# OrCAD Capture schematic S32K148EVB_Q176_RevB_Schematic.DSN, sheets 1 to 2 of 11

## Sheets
1 08. SAI AUDIO: size B; title: S32K148EVB-Q176; rev: B; company: NXP Semiconductors; note: SCH-29559 PDF: SPF-29559; note: 6501 William Cannon Drive West; note: Austin, TX 78735-8598
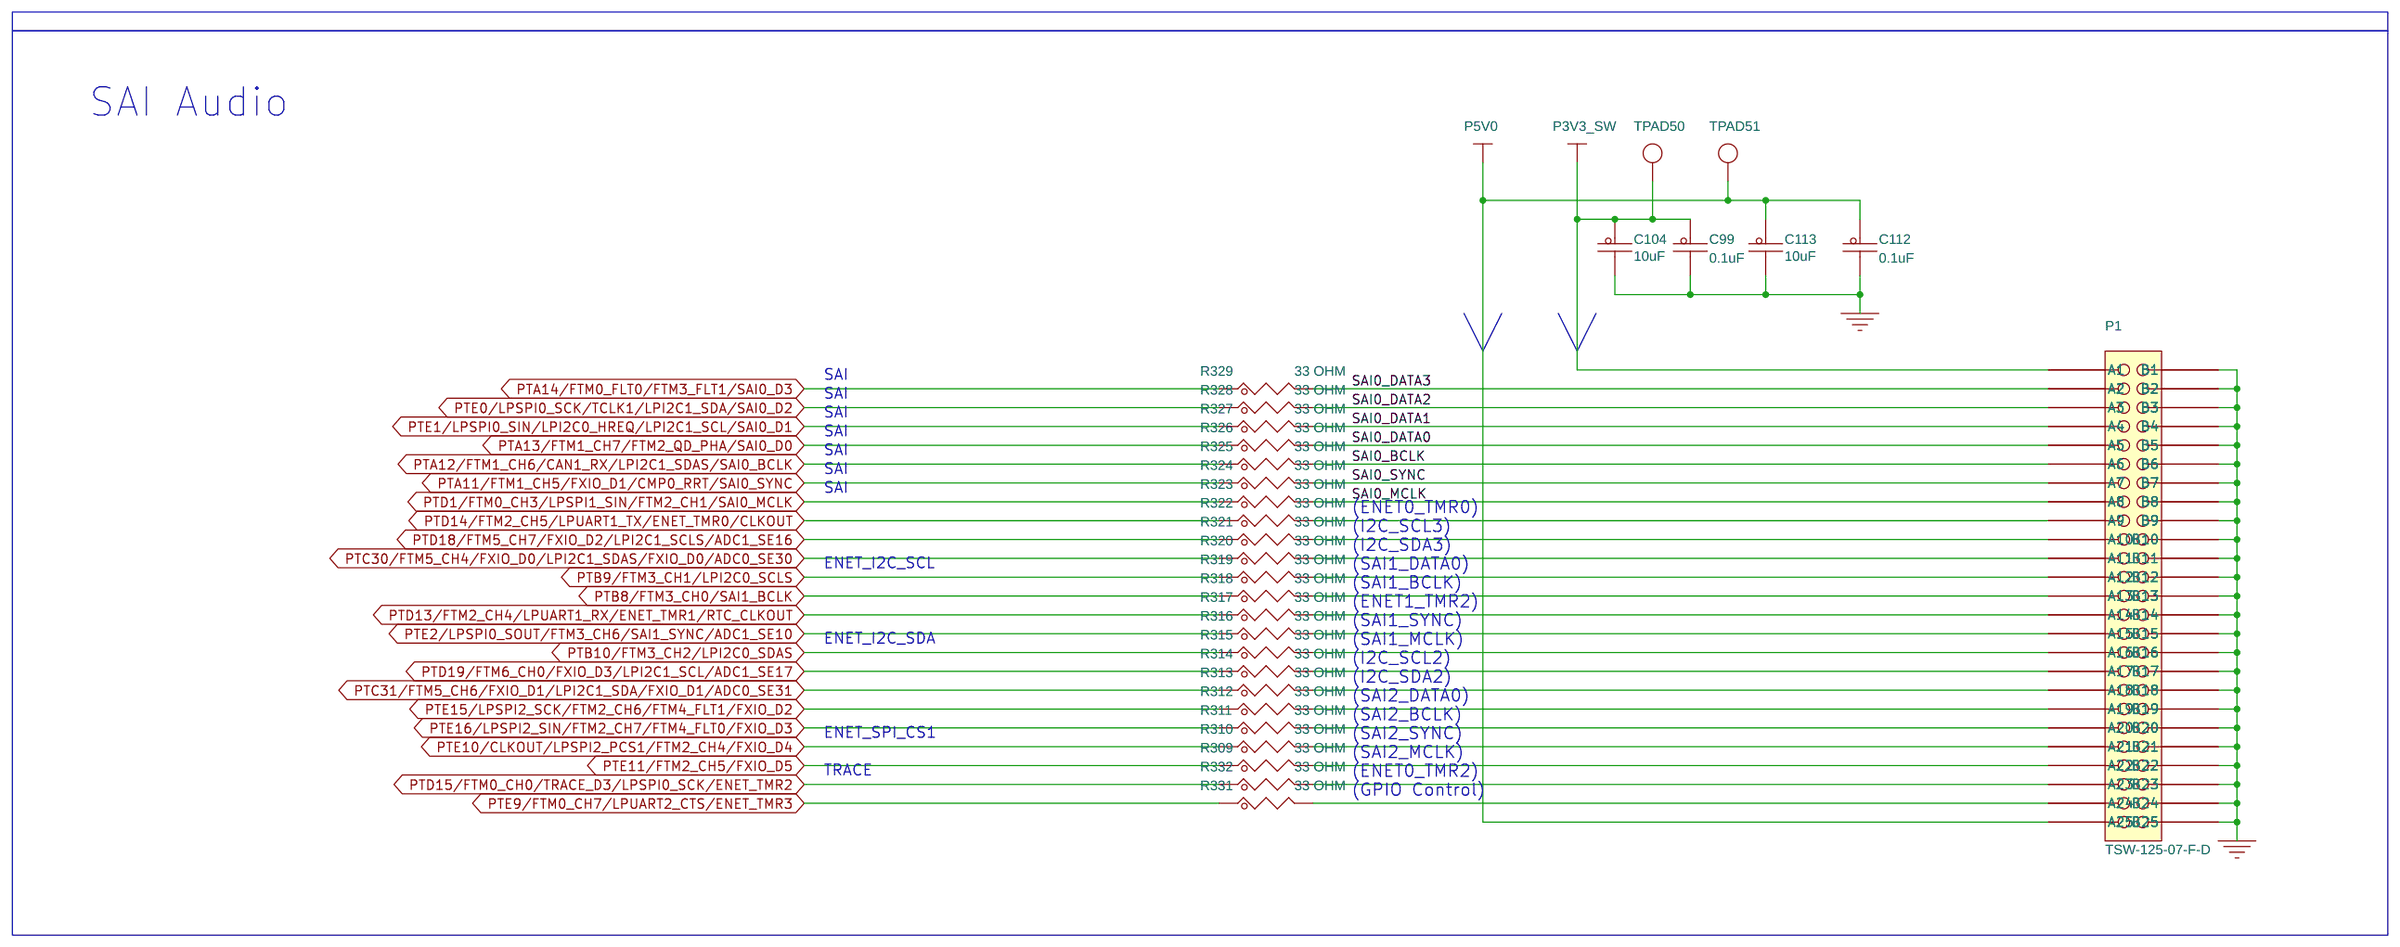
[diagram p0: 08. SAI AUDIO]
2 02. PWR SUPPLY: size D; company: Freescale Semiconductor; note: SCH-29642 PDF: SPF-29642
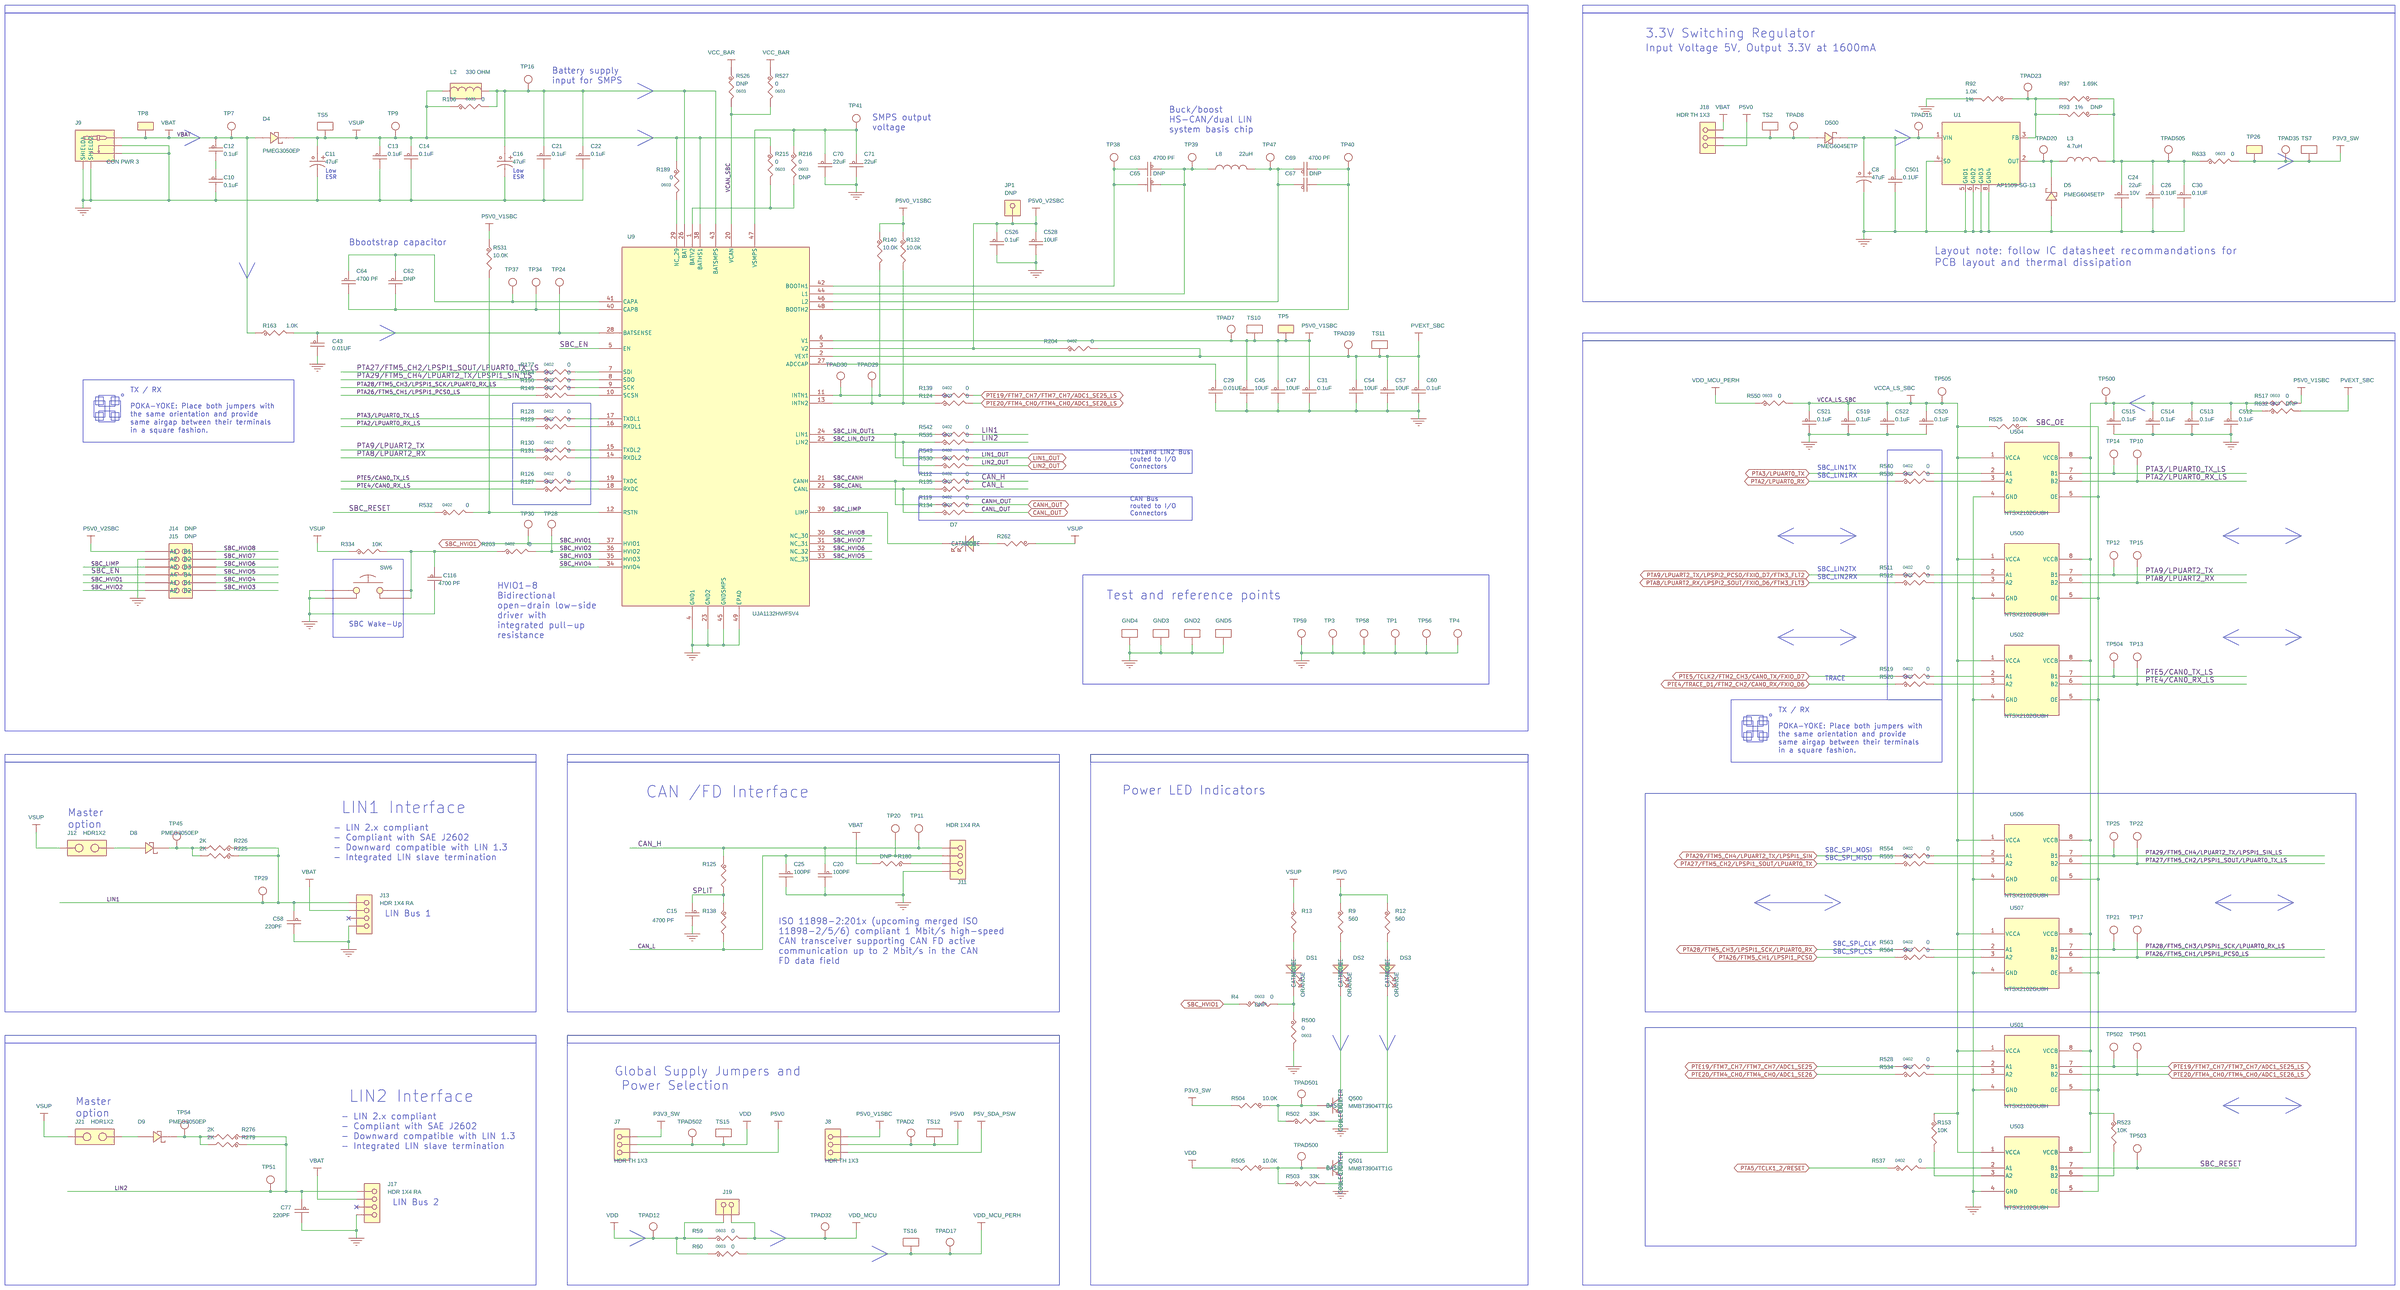
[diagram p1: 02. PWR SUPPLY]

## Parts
sheet 02. PWR SUPPLY
C8  47uF  [cce6p8x6p8]
C10  0.1uF  [CC0402_25]
C11  47uF  [cce6p8x6p8]
C12  0.1uF  [CC0402_25]
C13  0.1uF  [CC0402_25]
C14  0.1uF  [CC0402_25]
C15  4700 PF  [CC0603_OV]
C16  47uF  [cce6p8x6p8]
C20  100PF  [CC0402_25]
C21  0.1uF  [CC0402_25]
C22  0.1uF  [CC0402_25]
C24  22uF  [CC0603_OV]
C25  100PF  [CC0402_25]
C26  0.1UF  [CC0603_OV]
C29  0.01UF  [CC0402_25]
C30  0.1UF  [CC0603_OV]
C31  0.1uF  [CC0402_25]
C43  0.01UF  [CC0402_25]
C45  10UF  [CC0805_OV]
C47  10UF  [CC0805_OV]
C54  10UF  [CC0805_OV]
C57  10UF  [CC0805_OV]
C58  220PF  [CC0603_OV]
C60  0.1uF  [CC0402_25]
C62  4700 PF  [CC0603_OV]
C63  4700 PF  [CC0603_OV]
C64  4700 PF  [CC0603_OV]
C65  4700 PF  [CC0603_OV]
C67  4700 PF  [CC0603_OV]
C69  4700 PF  [CC0603_OV]
C70  22uF  [CC1210]
C71  22uF  [CC1210]
C77  220PF  [CC0603_OV]
C116  4700 PF  [CC0603_OV]
C501  0.1UF  [CC0603_OV]
C512  0.1uF  [CC0402_25]
C513  0.1uF  [CC0402_25]
C514  0.1uF  [CC0402_25]
C515  0.1uF  [CC0402_25]
C519  0.1uF  [CC0402_25]
C520  0.1uF  [CC0402_25]
C521  0.1uF  [CC0402_25]
C522  0.1uF  [CC0402_25]
C526  0.1uF  [CC0402_25]
C528  10UF  [CC0805_OV]
D4  PMEG3050EP  [sod-128]
D5  PMEG6045ETP  [sod-128]
D7  LY L29K-H1K2-26-Z  [LED_0603]
D8  PMEG3050EP  [sod-128]
D9  PMEG3050EP  [sod-128]
D500  PMEG6045ETP  [sod-128]
DS1  ORANGE  [led2_2p1x1p5_nsp]
DS2  ORANGE  [led2_2p1x1p5_nsp]
DS3  ORANGE  [led2_2p1x1p5_nsp]
GND2  5006  [tp_th_063]
GND3  5006  [tp_th_063]
GND4  5006  [tp_th_063]
GND5  5006  [tp_th_063]
J7  HDR TH 1X3  [HDR103]
J8  HDR TH 1X3  [HDR103]
J9  CON PWR 3  [con3_pwr_jack_th_pj051a]
J11  HDR 1X4 RA  [con_hdr_4m_100_th_ra]
J12  HDR1X2  [hdr1x2_5p48x2p69]
J13  HDR 1X4 RA  [con_hdr_4m_100_th_ra]
J14  HDR_2X2  [hdr2x2_50mil]
J15  HDR_2X4  [hdr2x4_50mil]
J17  HDR 1X4 RA  [con_hdr_4m_100_th_ra]
J18  HDR TH 1X3  [HDR103]
J19  HDR_1X2  [HDR102]
J21  HDR1X2  [hdr1x2_5p48x2p69]
JP1  HDR 1X1  [hdr101_045t]
L2  330 OHM  [ind_1608]
L3  4.7uH  [ind_5p2x5p2]
L8  22uH  [ind2_6p5x6p2mm_sm]
Q500  MMBT3904TT1G  [sc_75]
Q501  MMBT3904TT1G  [sc_75]
R4  0  [RC0603]
R9  560  [RC0603]
R12  560  [RC0603]
R13  1.8K  [RC0603]
R59  0  [RC0603]
R60  0  [RC0603]
R92  1.0K  [RC0402_25]
R93  3.09K  [RC0402_25]
R97  1.69K  [RC0402_25]
R106  0  [RC0603]
R112  0  [RC0402_25]
R119  0  [RC0402_25]
R124  0  [RC0402_25]
R125  60.4  [RC1206_OV]
R126  0  [RC0402_25]
R127  0  [RC0402_25]
R128  0  [RC0402_25]
R129  0  [RC0402_25]
R130  0  [RC0402_25]
R131  0  [RC0402_25]
R132  10.0K  [RC0402_25]
R134  0  [RC0402_25]
R135  0  [RC0402_25]
R138  60.4  [RC1206_OV]
R139  0  [RC0402_25]
R140  10.0K  [RC0402_25]
R149  0  [RC0402_25]
R150  0  [RC0402_25]
R153  10K  [RC0603_OV]
R154  0  [RC0402_25]
R163  1.0K  [RC0603_OV]
R177  0  [RC0402_25]
R180  0  [RC0805_OV]
R189  0  [RC0603]
R203  0  [RC0402_25]
R204  0  [RC0402_25]
R215  0  [RC0603]
R216  0  [RC0603]
R225  2K  [RC0805_OV]
R226  2K  [RC0805_OV]
R262  1.8K  [RC0603]
R276  2K  [RC0805_OV]
R279  2K  [RC0805_OV]
R334  10K  [RC0603_OV]
R500  0  [RC0603]
R502  33K  [RC0402_25]
R503  33K  [RC0402_25]
R504  10.0K  [RC0402_25]
R505  10.0K  [RC0402_25]
R511  0  [RC0402_25]
R512  0  [RC0402_25]
R517  0  [RC0603]
R519  0  [RC0402_25]
R520  0  [RC0402_25]
R523  10K  [RC0603_OV]
R525  10.0K  [RC0402_25]
R526  0  [RC0603]
R527  0  [RC0603]
R528  0  [RC0402_25]
R530  0  [RC0402_25]
R531  10.0K  [RC0402_25]
R532  0  [RC0402_25]
R534  0  [RC0402_25]
R535  0  [RC0402_25]
R536  0  [RC0402_25]
R537  0  [RC0402_25]
R540  0  [RC0402_25]
R542  0  [RC0402_25]
R543  0  [RC0402_25]
R550  0  [RC0603]
R554  0  [RC0402_25]
R555  0  [RC0402_25]
R563  0  [RC0402_25]
R564  0  [RC0402_25]
R632  0  [RC0603]
R633  0  [RC0603]
SW6  EVQ-P2402W  [sw4_spst_4p8X3p6_2p5]
TP1  TPAD_028  [TPAD_028]
TP3  TPAD_028  [TPAD_028]
TP4  TPAD_028  [TPAD_028]
TP5  TEST_POINT  [tp_th_063]
TP7  TPAD_028  [TPAD_028]
TP8  TEST_POINT  [tp_th_063]
TP9  TPAD_028  [TPAD_028]
TP10  TPAD_028  [TPAD_028]
TP11  TPAD_028  [TPAD_028]
TP12  TPAD_028  [TPAD_028]
TP13  TPAD_028  [TPAD_028]
TP14  TPAD_028  [TPAD_028]
TP15  TPAD_028  [TPAD_028]
TP16  TPAD_028  [TPAD_028]
TP17  TPAD_028  [TPAD_028]
TP20  TPAD_028  [TPAD_028]
TP21  TPAD_028  [TPAD_028]
TP22  TPAD_028  [TPAD_028]
TP24  TPAD_028  [TPAD_028]
TP25  TPAD_028  [TPAD_028]
TP26  TEST_POINT  [tp_th_063]
TP28  TPAD_028  [TPAD_028]
TP29  TPAD_028  [TPAD_028]
TP30  TPAD_028  [TPAD_028]
TP34  TPAD_028  [TPAD_028]
TP37  TPAD_028  [TPAD_028]
TP38  TPAD_028  [TPAD_028]
TP39  TPAD_028  [TPAD_028]
TP40  TPAD_028  [TPAD_028]
TP41  TPAD_028  [TPAD_028]
TP45  TPAD_028  [TPAD_028]
TP47  TPAD_028  [TPAD_028]
TP51  TPAD_028  [TPAD_028]
TP54  TPAD_028  [TPAD_028]
TP56  TPAD_028  [TPAD_028]
TP58  TPAD_028  [TPAD_028]
TP59  TPAD_028  [TPAD_028]
TP500  TPAD_028  [TPAD_028]
TP501  TPAD_028  [TPAD_028]
TP502  TPAD_028  [TPAD_028]
TP503  TPAD_028  [TPAD_028]
TP504  TPAD_028  [TPAD_028]
TP505  TPAD_028  [TPAD_028]
TPAD2  TPAD_030  [TPAD_030]
TPAD7  TPAD_030  [TPAD_030]
TPAD8  TPAD_030  [TPAD_030]
TPAD12  TPAD_030  [TPAD_030]
TPAD15  TPAD_030  [TPAD_030]
TPAD17  TPAD_030  [TPAD_030]
TPAD20  TPAD_030  [TPAD_030]
TPAD23  TPAD_030  [TPAD_030]
TPAD29  TPAD_030  [TPAD_030]
TPAD30  TPAD_030  [TPAD_030]
TPAD32  TPAD_030  [TPAD_030]
TPAD35  TPAD_030  [TPAD_030]
TPAD39  TPAD_030  [TPAD_030]
TPAD500  TPAD_030  [TPAD_030]
TPAD501  TPAD_030  [TPAD_030]
TPAD502  TPAD_030  [TPAD_030]
TPAD505  TPAD_030  [TPAD_030]
TS2  TESTLOOP  [testpoint_135_070mil]
TS5  TESTLOOP  [testpoint_135_070mil]
TS7  TESTLOOP  [testpoint_135_070mil]
TS10  TESTLOOP  [testpoint_135_070mil]
TS11  TESTLOOP  [testpoint_135_070mil]
TS12  TESTLOOP  [testpoint_135_070mil]
TS15  TESTLOOP  [testpoint_135_070mil]
TS16  TESTLOOP  [testpoint_135_070mil]
U1  AP1509-SG-13  [SO8_1P27_4X5]
U9  UJA1132HWF5V4  [htqfp48_0p65_10x10_ep_5mm]
U500  NTSX2102GU8H  [xqfn8_1p45x1p25mm]
U501  NTSX2102GU8H  [xqfn8_1p45x1p25mm]
U502  NTSX2102GU8H  [xqfn8_1p45x1p25mm]
U503  NTSX2102GU8H  [xqfn8_1p45x1p25mm]
U504  NTSX2102GU8H  [xqfn8_1p45x1p25mm]
U506  NTSX2102GU8H  [xqfn8_1p45x1p25mm]
U507  NTSX2102GU8H  [xqfn8_1p45x1p25mm]
sheet 08. SAI AUDIO
C99  0.1uF  [CC0402_25]
C104  10uF  [CC0603_OV]
C112  0.1uF  [CC0402_25]
C113  10uF  [CC0603_OV]
P1  TSW-125-07-F-D  [HDR225]
R309  33 OHM  [RC0402_25]
R310  33 OHM  [RC0402_25]
R311  33 OHM  [RC0402_25]
R312  33 OHM  [RC0402_25]
R313  33 OHM  [RC0402_25]
R314  33 OHM  [RC0402_25]
R315  33 OHM  [RC0402_25]
R316  33 OHM  [RC0402_25]
R317  33 OHM  [RC0402_25]
R318  33 OHM  [RC0402_25]
R319  33 OHM  [RC0402_25]
R320  33 OHM  [RC0402_25]
R321  33 OHM  [RC0402_25]
R322  33 OHM  [RC0402_25]
R323  33 OHM  [RC0402_25]
R324  33 OHM  [RC0402_25]
R325  33 OHM  [RC0402_25]
R326  33 OHM  [RC0402_25]
R327  33 OHM  [RC0402_25]
R328  33 OHM  [RC0402_25]
R329  33 OHM  [RC0402_25]
R331  33 OHM  [RC0402_25]
R332  33 OHM  [RC0402_25]
TPAD50  TPAD_030  [TPAD_030]
TPAD51  TPAD_030  [TPAD_030]

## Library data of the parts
C8 C11 C16 = CAP_POL: CAP ALEL 47uF 25V 20% -- SMT; AGILE_PN: 150-79138; CAD_APPROVED: Yes; HEIGHT: 6.1MM; MFG_NAME01: NICHICON; MFG_PN01: UUD1E470MCL1GS; ROHS: Yes; Tolerance: 20%; VOLTAGE: 25V
C10 C12-C14 C21 C22 C31 C60 C512-C515 C519-C522 C526 = CAP_NP: CAP CER 0.1uF 50V 10% X7R 0402; AGILE_PN: 150-79069; CAD_APPROVED: Yes; FPLIST: CC0402_25,CC0402_HD,0402_CC; HEIGHT: 0.55MM; MFG_NAME01: MURATA; MFG_PN01: GRM155R71H104KE14D; ROHS: Yes; Tolerance: 10%; VOLTAGE: 50V
C15 C63 C64 C69 C116 = CAP_NP: CAP CER 4700PF 50V 5% X7R 0603; AGILE_PN: 150-30045; CAD_APPROVED: Yes; FPLIST: CC0603_OV,CC0603,0603_CC; HEIGHT: 1.0MM; MFG_NAME01: AVX; MFG_PN01: 06035C472JAT2A; ROHS: Yes; Tolerance: 5%; VOLTAGE: 50V
C20 C25 = CAP_NP: CAP CER 100PF 50V 5% C0G 0402; AGILE_PN: 150-30247; CAD_APPROVED: Yes; FPLIST: CC0402_25,CC0402_HD,0402_CC; HEIGHT: 0.55MM; MFG_NAME01: KEMET; MFG_PN01: C0402C101J5GAC; ROHS: Yes; Temp_Range: -55°C to +125°C; Tolerance: 5%; VOLTAGE: 50V
C24 = CAP_NP: CAP CER 22uF 10V 20% X5R 0603; AGILE_PN: 150-79530; CAD_APPROVED: Yes; FPLIST: CC0603_OV,CC0603,0603_CC; HEIGHT: 1MM; MFG_NAME01: TDK; MFG_PN01: C1608X5R1A226M080AC; ROHS: Yes; Tolerance: 20%; VOLTAGE: 10V
C26 C30 C501 = CAP_NP: CAP CER 0.10UF 25V 10% X7R 0603; AGILE_PN: 150-75016; CAD_APPROVED: Yes; FPLIST: CC0603_OV,CC0603,0603_CC; HEIGHT: 0.97 MM; MFG_NAME01: KEMET; MFG_PN01: C0603C104K3RAC; ROHS: Yes; TOL: 10%; Tolerance: 10%; VOLTAGE: 25V
C29 C43 = CAP_NP: CAP CER 0.01UF 50V 10% X7R 0402; AGILE_PN: 150-30114; CAD_APPROVED: Yes; FPLIST: CC0402_25,CC0402_HD,0402_CC; HEIGHT: 0.74 MM; MFG_NAME01: WALSIN TECHNOLOGY CORP.; MFG_PN01: 0402B103K500CT; ROHS: Yes; Tolerance: 10%; VOLTAGE: 50V
C45 C47 C54 C57 C528 = CAP_NP: CAP CER 10UF 10V 10% X7R 0805; AGILE_PN: 150-78501; CAD_APPROVED: Yes; FPLIST: CC0603_OV,CC0603,0603_CC; HEIGHT: 1.4MM; MFG_NAME01: Murata; MFG_PN01: GRM21BR71A106KE51L; ROHS: Yes; Tolerance: 10%; VOLTAGE: 10V
C58 C77 = CAP_NP: CAP CER 220PF 50V 10% X7R 0603; AGILE_PN: 150-75200; CAD_APPROVED: Yes; FPLIST: CC0603_OV,CC0603,0603_CC; HEIGHT: 0.9652MM; MFG_NAME01: KEMET; MFG_PN01: C0603C221K5RAC; ROHS: Yes; Tolerance: 10%; VOLTAGE: 50V
C62 C65 C67 = CAP_NP: CAP CER 4700PF 50V 5% X7R 0603; AGILE_PN: 150-30045; ASSY_OPT: DNP; CAD_APPROVED: Yes; FPLIST: CC0603_OV,CC0603,0603_CC; HEIGHT: 1.0MM; MFG_NAME01: AVX; MFG_PN01: 06035C472JAT2A; ROHS: Yes; Tolerance: 5%; VOLTAGE: 50V
C70 C71 = CAP_NP: CAP CER 22uF 25V 10% X7R 1210; AGILE_PN: 150-79198; CAD_APPROVED: Yes; FPLIST: CC1210,1210_CC; HEIGHT: 2.7MM; MFG_NAME01: MURATA; MFG_PN01: GRM32ER71E226KE15L; ROHS: Yes; Tolerance: 10%; VOLTAGE: 25V
D4 D8 D9 = DIODE_SCHTKY: DIODE SCH RECT 5A 30V AEC-Q101 SOD128; AGILE_PN: 480-78776; CAD_APPROVED: Yes; HEIGHT: 1.1 MM; MFG_NAME01: NEXPERIA; MFG_PN01: PMEG3050EP,115; ROHS: Yes
D5 D500 = DIODE_SCHTKY: DIODE SCHOTTKY 60V 4.5A AEC-Q101 SOD128; AGILE_PN: 480-79703; CAD_APPROVED: Yes; HEIGHT: 1.1MM; MFG_NAME01: NEXPERIA; MFG_PN01: PMEG6045ETPX; ROHS: Yes
D7 = LED: LED YEL SGL 20mA 1.8V 0603; AGILE_PN: 370-76707; CAD_APPROVED: Yes; HEIGHT: 0.67MM; MFG_NAME01: OSRAM; ROHS: Yes; Temp_Range: -40C to +100c
DS1-DS3 = LED: LED ORG SGL 20MA SMT; AGILE_PN: 370-76636; CAD_APPROVED: Yes; FPLIST: 1206ld,1206ld_1A2C; HEIGHT: 1.4MM; MFG_NAME01: OSRAM; MFG_PN01: LO M67K-K2M1-24-0-2-R18-Z; PRIORITY_PN: 048-01001; ROHS: Yes
GND2-GND5 = TEST_POINT_3: TEST POINT BLK 70X220 MIL TH; AGILE_PN: 210-30155; CAD_APPROVED: Yes; HEIGHT: 5.6MM; MFG_NAME01: Keystone Electronics; ROHS: Yes
J7 J8 J18 = CONN_HDR_3X1: HDR 1x3 TH 100MIL SP 343H AU 100L; AGILE_PN: 210-80734; CAD_APPROVED: Yes; HEIGHT: 8.72MM; MFG_NAME01: SAMTEC; MFG_PN01: TSW-103-07-F-S; ROHS: Yes
J9 = DC_POWER_JACK_SHD: CON 3 PWR JACK RA TH 295H -- NI 98L; AGILE_PN: 210-79945; CAD_APPROVED: Yes; HEIGHT: 7.5MM; MFG_NAME01: CUI INC; MFG_PN01: PJ-051A; ROHS: Yes
J11 J13 J17 = CONN_HDR_4X1: HDR 1X4 TH RA 100MIL SP 268H AU 124L; AGILE_PN: 210-79929; CAD_APPROVED: Yes; HEIGHT: 6.81MM; MFG_NAME01: MOLEX; MFG_PN01: 0022122041; ROHS: Yes
J12 J21 = JUMPER_2_2mm: HDR 1X2 TH 100MIL SP 342H AU 118L; AGILE_PN: 210-80468; CAD_APPROVED: Yes; FPLIST: HDR102,SH_HDR102_BOTTOM; HEIGHT: 8.69MM; MFG_NAME01: WURTH ELEKTRONIK EISOS GMBH & CO. KG; MFG_PN01: 61300211121; ROHS: Yes
J14 = CONN_HDR_2X2: HDR 2X2 TH 50MIL CTR 165H AU 91L; AGILE_PN: 210-80215; ASSY_OPT: DNP; CAD_APPROVED: Yes; HEIGHT: 4.2MM; MFG_NAME01: SULLINS ELECTRONICS CORP; MFG_PN01: GRPB022VWVN-RC; ROHS: Yes
J15 = CONN_HDR_4X2: HDR 2X4 TH 50MIL CTR 165H AU 91L; AGILE_PN: 210-80214; ASSY_OPT: DNP; CAD_APPROVED: Yes; HEIGHT: 4.2MM; MFG_NAME01: SULLINS ELECTRONICS CORP; MFG_PN01: GRPB042VWVN-RC; ROHS: Yes
J19 = CONN_HDR_2X1: HDR 1X2 TH 100MIL SP 378H AU 130L; AGILE_PN: 210-75673; CAD_APPROVED: Yes; HEIGHT: 9.6 MM; MFG_NAME01: TYCO ELECTRONICS; MFG_PN01: 826629-2; ROHS: Yes
JP1 = CONN_HDR_1X1: HDR 1X1 TH -- 330H SN 115L; AGILE_PN: 210-79455; ASSY_OPT: DNP; CAD_APPROVED: Yes; FPLIST: hdr101_045t,HDR101; HEIGHT: 8.59MM; MFG_NAME01: MOLEX; MFG_PN01: 87891-0106; ROHS: Yes
L2 = BEAD: IND FER BEAD 330OHM@100MHZ 1.7A 0603; AGILE_PN: 180-78156; CAD_APPROVED: Yes; FPLIST: ind_1608,0603_CC; HEIGHT: 0.95MM; MFG_NAME01: TDK; MFG_PN01: MPZ1608S331A; PART_TYPE: FERRITE\BEAD; ROHS: Yes; Tolerance: 25%
L3 = INDUCTOR: IND WW PWR 4.7UH@40MHZ 3A 30% SMT; AGILE_PN: 180-78209; CAD_APPROVED: Yes; HEIGHT: 2.2MM; MFG_NAME01: MURATA; MFG_PN01: LQH5BPN4R7NT0; PART_TYPE: POWER; ROHS: Yes; TOL: 30%; Tolerance: 30%
L8 = INDUCTOR: IND PWR 22uH@100kHz 1.3A 20% AUTO SMT; AGILE_PN: 180-78192; CAD_APPROVED: Yes; HEIGHT: 4.8MM; MFG_NAME01: TDK; MFG_PN01: CLF6045NIT-220M-D; PART_TYPE: INDUCTOR\POWER; ROHS: Yes; Tolerance: 20%
Q500 Q501 = NPN: TRAN NPN GEN AMP 200MA 40V AEC-Q101 SC75; AGILE_PN: 480-75477; CAD_APPROVED: Yes; HEIGHT: 0.9 MM; MFG_NAME01: ON SEMICONDUCTOR; ROHS: Yes
R4 R216 R526 R632 = RES: RES MF ZERO OHM 1/10W -- AEC-Q200 0603; AGILE_PN: 470-75407; ASSY_OPT: DNP; CAD_APPROVED: Yes; FPLIST: RC0603_OV,RC0603,R603-X2,0603_CC; HEIGHT: 0.6MM; MFG_NAME01: PANASONIC; MFG_PN01: ERJ-3GEY0R00V; PCKG: 0603; ROHS: Yes; Tolerance: 1%
R9 R12 = RES: RES MF 560 1/10W 5% 0603; AGILE_PN: 470-30301; CAD_APPROVED: Yes; FPLIST: RC0603_OV,RC0603,0603_CC; HEIGHT: 0.6MM; MFG_NAME01: YAGEO AMERICA; MFG_PN01: RC0603JR-07560RL; ROHS: Yes; SIGNAL_MODEL: DEFAULT_RESISTOR_560.000000OHM_2_1; TOL: 5%; Tolerance: 5%
R13 R262 = RES: RES MF 1.8K 1/10W 5% 0603; AGILE_PN: 470-79996; CAD_APPROVED: Yes; FPLIST: RC0603_OV,RC0603,0603_CC; HEIGHT: 0.60MM; MFG_NAME01: WALSIN TECHNOLOGY CORP.; MFG_PN01: WR06X182JTL; ROHS: Yes; TOL: 5%; Tolerance: 5%
R59 R60 R106 R189 R215 R500 R517 R527 R550 R633 = RES: RES MF ZERO OHM 1/10W -- AEC-Q200 0603; AGILE_PN: 470-75407; CAD_APPROVED: Yes; FPLIST: RC0603_OV,RC0603,R603-X2,0603_CC; HEIGHT: 0.6MM; MFG_NAME01: PANASONIC; MFG_PN01: ERJ-3GEY0R00V; PCKG: 0603; ROHS: Yes; Tolerance: 1%
R92 = RES: RES MF 1.0K 1/16W 1% 0402; AGILE_PN: 470-76037; CAD_APPROVED: Yes; FPLIST: RC0402_25,RC0402_HD,RC0402_X2,0402_CC; HEIGHT: 0.4MM; MFG_NAME01: YAGEO AMERICA; MFG_PN01: RC0402FR-071KL; ROHS: Yes; Tolerance: 1%
R93 = RES: RES MF 3.09K  1/16W 1% 0402; AGILE_PN: 470-30888; ASSY_OPT: DNP; CAD_APPROVED: Yes; FPLIST: RC0402_25,RC0402_HD,0402_CC; HEIGHT: 0.40 MM; MFG_NAME01: YAGEO AMERICA; MFG_PN01: RT0402FRE073K09L; ROHS: Yes; Tolerance: 1%
R97 = RES: RES MF 1.69K  1/10W 1% AEC-Q200 0402; AGILE_PN: 470-81572; CAD_APPROVED: Yes; FPLIST: RC0402_25,RC0402_HD,0402_CC; HEIGHT: 0.40 MM; MFG_NAME01: KOA SPEER; MFG_PN01: RK73H1ETTP1691F; ROHS: Yes; Temp_Range: -55C to +155C; Tolerance: 1%
R112 R119 R124 R126-R131 R134 R135 R139 R149 R150 R154 R177 R203 R204 R511 R512 R519 R520 R528 R530 R532 R534-R537 R540 R542 R543 R554 R555 R563 R564 = RES: RES MF ZERO OHM 1/16W -- AEC-Q200 0402; AGILE_PN: 470-80742; CAD_APPROVED: Yes; FPLIST: RC0402_25,RC0402_HD,0402_CC; HEIGHT: 0.45 MM; MFG_NAME01: VISHAY INTERTECHNOLOGY; MFG_PN01: CRCW04020000Z0ED; PCKG: 0402; ROHS: Yes
R125 R138 = RES: RES MF 60.4 OHM 1/4W 1% 1206; AGILE_PN: 470-78243; CAD_APPROVED: Yes; FPLIST: RC1206_OV,RC1206,1206_CC; HEIGHT: 0.6MM; MFG_NAME01: VISHAY INTERTECHNOLOGY; MFG_PN01: CRCW120660R4FKEA; ROHS: Yes; Tolerance: 1%
R132 R140 R504 R505 R525 R531 = RES: RES MF 10.0K 1/16W 1% AEC-Q200 0402; AGILE_PN: 470-75416; CAD_APPROVED: Yes; FPLIST: RC0402_25,RC0402_HD,0402_CC; HEIGHT: 0.4MM; MFG_NAME01: KOA SPEER; MFG_PN01: RK73H1ETTP1002F; PRIORITY_PN: 006-00552; ROHS: Yes; SIGNAL_MODEL: DEFAULT_RESISTOR_10000OHM_2_1; TOL: 1%; Tolerance: 1%
R153 R523 = RES: RES MF 10K 1/10W 0.1% AEC-Q200 0603; AGILE_PN: 470-80764; CAD_APPROVED: Yes; FPLIST: RC0603_OV,RC0603,0603_CC; HEIGHT: 0.55MM; MFG_NAME01: Vishay Intertechnology; MFG_PN01: TNPW060310K0BEEN; ROHS: Yes; Tolerance: 0.1%
R163 = RES: RES MF 1.00K 1/16W 0.1% 0603; AGILE_PN: 470-75915; CAD_APPROVED: Yes; FPLIST: RC0603_OV,RC0603,0603_CC; HEIGHT: 0.55MM; MFG_NAME01: KOA SPEER; MFG_PN01: RN731JTTD1001B25; ROHS: Yes; Tolerance: 0.1%
R180 = RES: RES MF ZERO 1/8W AEC-Q200 0805; AGILE_PN: 470-80547; ASSY_OPT: DNP; CAD_APPROVED: Yes; FPLIST: RC0805_OV,RC0805,RC0805_OV_3P,0805_CC; HEIGHT: 0.65 MM; MFG_NAME01: ROHM; MFG_PN01: MCR10EZPJ000; ROHS: Yes
R225 R226 R276 R279 = RES: RES MF 2K 1/8W 1% 0805; AGILE_PN: 470-76341; CAD_APPROVED: Yes; FPLIST: RC0805_OV,RC0805,0805_CC; HEIGHT: 0.65MM; MFG_NAME01: BOURNS; MFG_PN01: CR0805-FX-2001ELF; ROHS: Yes; Tolerance: 1%
R334 = RES: RES MF 10K 1/10W 1% AEC-Q200 0603; AGILE_PN: 470-80526; CAD_APPROVED: Yes; FPLIST: RC0603_OV,RC0603,0603_CC; HEIGHT: 0.55 MM; MFG_NAME01: VISHAY INTERTECHNOLOGY; MFG_PN01: CRCW060310K0FKEA; ROHS: Yes; Tolerance: 1%
R502 R503 = RES: RES MF 33K  1/16W 1% 0402; AGILE_PN: 470-31004; CAD_APPROVED: Yes; FPLIST: RC0402_25,RC0402_HD,0402_CC; HEIGHT: 0.40 MM; MFG_NAME01: YAGEO AMERICA; MFG_PN01: RC0402FR-0733KL; ROHS: Yes; Temp_Range: -55°C ~ 155°C; Tolerance: 1%
SW6 = EDGE_MOUNT_PB_SW_2: SW SPST PB NO 0.02A 15V SMT; AGILE_PN: 510-77992; CAD_APPROVED: Yes; HEIGHT: 2.7 MM; MFG_NAME01: Panasonic; ROHS: Yes
TP1 TP3 TP4 TP7 TP9-TP17 TP20-TP22 TP24 TP25 TP28-TP30 TP34 TP37-TP41 TP45 TP47 TP51 TP54 TP56 TP58 TP59 TP500-TP505 = TESTLOOP: TEST POINT PAD 28MIL DIA SMT, NO PART TO ORDER; AGILE_PN: 211-79313; CAD_APPROVED: Yes; HEIGHT: 0.1 MM; MFG_NAME01: N/A; MFG_PN01: N/A; ROHS: Yes
TP5 TP8 TP26 = TEST_POINT_0: TEST POINT RED 70X220 MIL TH; AGILE_PN: 210-30156; CAD_APPROVED: Yes; HEIGHT: 5.59MM; MFG_NAME01: KEYSTONE ELECTRONICS; MFG_PN01: 5005; ROHS: Yes
TPAD2 TPAD7 TPAD8 TPAD12 TPAD15 TPAD17 TPAD20 TPAD23 TPAD29 TPAD30 TPAD32 TPAD35 TPAD39 TPAD50 TPAD51 TPAD500-TPAD502 TPAD505 = TestLoop: TEST POINT PAD 30MIL DIA SMT, NO PART TO ORDER; AGILE_PN: 211-76642; CAD_APPROVED: Yes; HEIGHT: 0.1MM; MFG_NAME01: NOTACOMPONENT; MFG_PN01: NOTACOMPONENT; ROHS: Yes
TS2 TS5 TS7 TS10-TS12 TS15 TS16 = TEST_POINT_4: TEST POINT PAD SIZE 3.4MM X 1.8MM SMT; AGILE_PN: 211-75906; CAD_APPROVED: Yes; HEIGHT: 1.53 MM; MFG_NAME01: KEYSTONE ELECTRONICS; MFG_PN01: 5015; PRIORITY_PN: 922-00014; ROHS: Yes
U1 = AP1509_ADJ: IC SW REG CNV BUCK ASYN ADJ 2A 4.5-22V SOP8; AGILE_PN: 315-80778; CAD_APPROVED: Yes; HEIGHT: 1.75MM; MFG_NAME01: Diodes Inc; ROHS: Yes
U9 = UJA1132HW_FD_HTQFP_48P_EP_7: IC XCVR SBC BUCK-BOOST HS-CAN-FD LIN HVIO 5V 500mA AEC-Q100 HTQFP48; AGILE_PN: 315-81276; CAD_APPROVED: Yes; HEIGHT: 1.2MM; MFG_NAME01: NXP SEMICONDUCTORS; ROHS: Yes
U500-U504 U506 U507 = NTSX2102GU8H_8P: IC DUAL SUPPLY XCVR 50 MBPS 5.5V XQFN8; AGILE_PN: 312-80763; CAD_APPROVED: Yes; HEIGHT: 0.5MM; MFG_NAME01: NXP Semiconductors; ROHS: Yes; VOLTAGE: 5.5V
C99 C112 = CAP_NP: CAP CER 0.1uF 16V 10% X7R AEC-Q200 0402; AGILE_PN: 150-79025; CAD_APPROVED: Yes; FPLIST: CC0402_25,CC0402_HD,0402_CC; HEIGHT: 0.55MM; MFG_NAME01: MURATA; MFG_PN01: GCM155R71C104KA55D; ROHS: Yes
C104 C113 = CAP_NP: CAP CER 10uF 25V 20% X5R 0603; AGILE_PN: 150-79272; CAD_APPROVED: Yes; FPLIST: CC0603_OV,CC0603,0603_CC; HEIGHT: 1MM; MFG_NAME01: Murata; MFG_PN01: GRM188R61E106MA73D; ROHS: Yes; TOL: 10%; Tolerance: 20%; VOLTAGE: 25V
P1 = CONN_HDR_25X2: HDR 2X25 TH 100MIL CTR 338H AU 100L; AGILE_PN: 210-81314; CAD_APPROVED: Yes; HEIGHT: 8.59MM; MFG_NAME01: SAMTEC; ROHS: Yes; Temp_Range: -55C to +125C
R309-R329 R331 R332 = RES: RES MF 33 OHM 1/10W 1% AEC-Q200  0402; AGILE_PN: 470-80961; CAD_APPROVED: Yes; FPLIST: RC0402_25,RC0402_HD,0402_CC; HEIGHT: 0.4 MM; MFG_NAME01: PANASONIC; MFG_PN01: ERJ2RKF33R0X; ROHS: Yes; Tolerance: 1%

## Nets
GND: C8.2 C10.2 C11.2 C13.2 C14.2 C15.2 C16.2 C20.2 C21.2 C22.2 C24.2 C25.2 C26.2 C29.2 C30.2 C31.2 C43.2 C45.2 C47.2 C54.2 C57.2 C58.2 C60.2 C70.2 C71.2 C77.2 C99.2 C104.2 C112.2 C113.2 C116.2 C501.2 C512.2 C513.2 C514.2 C515.2 C519.2 C520.2 C521.2 C522.2 C526.2 C528.2 D5.A GND2.1 GND3.1 GND4.1 GND5.1 J9.2 J9.3 J9.SH1(SHIELD1) J9.SH2(SHIELD2) J11.4 J13.4 J15.3(A2) J17.4 P1.2(B1) P1.4(B2) P1.6(B3) P1.8(B4) P1.10(B5) P1.12(B6) P1.14(B7) P1.16(B8) P1.18(B9) P1.20(B10) P1.22(B11) P1.24(B12) P1.26(B13) P1.28(B14) P1.30(B15) P1.32(B16) P1.34(B17) P1.36(B18) P1.38(B19) P1.40(B20) P1.42(B21) P1.44(B22) P1.46(B23) P1.48(B24) P1.50(B25) Q500.2(EMITTER) Q501.2(EMITTER) R92.2 R500.2 R502.2 R503.2 SW6.1 SW6.3 TP1.1(Pin1) TP3.1(Pin1) TP4.1(Pin1) TP56.1(Pin1) TP58.1(Pin1) TP59.1(Pin1) U1.4(SD) U1.5(GND1) U1.6(GND2) U1.7(GND3) U1.8(GND4) U9.4(GND1) U9.23(GND2) U9.45(GNDSMPS) U9.49(EPAD) U500.4(GND) U501.4(GND) U502.4(GND) U503.4(GND) U504.4(GND) U506.4(GND) U507.4(GND) ; also on sheet 3 4 5 6 7 8 9 11
P3V3_SW: C99.1 C104.1 J7.1 P1.1(A1) R504.2 R633.2 TP26.1 TPAD35.1(Pin1) TPAD50.1(Pin1) TS7.1 ; also on sheet 4 5 6 7 11
P5V0: C112.1 C113.1 J7.3 J8.2 J18.3 P1.49(A25) R9.1 R12.1 TPAD2.1(Pin1) TPAD51.1(Pin1) TS12.1 ; also on sheet 4 6 9 11
P5V0_V1SBC: C31.1 C45.1 C47.1 J8.1 R132.1 R140.1 R517.2 R526.1 R531.1 TP5.1 TPAD7.1(Pin1) TS10.1 U9.6(V1)
P5V0_V2SBC: C526.1 C528.1 J15.1(A1) JP1.1 R204.1 U9.3(V2)
P5V_SDA_PSW: J8.3 ; also on sheet 5
VBAT: C12.1 D4.A J9.1 J13.2 J17.2 J18.1 R163.1 R180.2 TP7.1(Pin1) TP8.1 ; also on sheet 11
VCCA_LS_SBC: C519.1 C520.1 C521.1 C522.1 R153.1 R525.2 R550.2 TP505.1(Pin1) U500.1(VCCA) U501.1(VCCA) U502.1(VCCA) U503.1(VCCA) U504.1(VCCA) U506.1(VCCA) U507.1(VCCA)
VDD: J7.2 J19.2 R59.1 R60.1 R505.2 TPAD12.1(Pin1) TPAD502.1(Pin1) TS15.1 ; also on sheet 5
VDD_MCU: J19.1 R59.2 TPAD32.1(Pin1) ; also on sheet 3
VDD_MCU_PERH: R60.2 R550.1 TPAD17.1(Pin1) TS16.1 ; also on sheet 3 4 6 9 11
CAN_H: C20.1 J11.1 R112.2 R125.1 TP11.1(Pin1)
CAN_L: C25.1 J11.2 R135.2 R138.2 TP20.1(Pin1)
CANH_OUT: R119.2 ; also on sheet 11
CANL_OUT: R134.2 ; also on sheet 11
LIN1: C58.1 J13.1 R225.1 R226.1 R542.2 TP29.1(Pin1)
LIN1_OUT: R543.2 ; also on sheet 11
LIN2: C77.1 J17.1 R276.1 R279.1 R535.2 TP51.1(Pin1)
LIN2_OUT: R530.2 ; also on sheet 11
PTA2/LPUART0_RX: R536.1 ; also on sheet 3 11
PTA2/LPUART0_RX_LS: R129.1 TP10.1(Pin1) U504.6(B2)
PTA3/LPUART0_TX: R540.1 ; also on sheet 3 11
PTA3/LPUART0_TX_LS: R128.1 TP14.1(Pin1) U504.7(B1)
PTA5/TCLK1_2/RESET: R537.1 ; also on sheet 3 4 5 11
PTA8/LPUART2_RX: R131.1 TP15.1(Pin1) U500.6(B2)
PTA8/LPUART2_RX/LPSPI2_SOUT/FXIO_D6/FTM3_FLT3: R512.1 ; also on sheet 3 11
PTA9/LPUART2_TX: R130.1 TP12.1(Pin1) U500.7(B1)
PTA9/LPUART2_TX/LPSPI2_PCS0/FXIO_D7/FTM3_FLT2: R511.1 ; also on sheet 3 11
PTA11/FTM1_CH5/FXIO_D1/CMP0_RRT/SAI0_SYNC: R324.1 ; also on sheet 3 11
PTA12/FTM1_CH6/CAN1_RX/LPI2C1_SDAS/SAI0_BCLK: R325.1 ; also on sheet 3 11
PTA13/FTM1_CH7/FTM2_QD_PHA/SAI0_D0: R326.1 ; also on sheet 3 11
PTA14/FTM0_FLT0/FTM3_FLT1/SAI0_D3: R329.1 ; also on sheet 3 11
PTA26/FTM5_CH1/LPSPI1_PCS0: R564.1 ; also on sheet 3 11
PTA26/FTM5_CH1/LPSPI1_PCS0_LS: R149.1 TP17.1(Pin1) U507.6(B2)
PTA27/FTM5_CH2/LPSPI1_SOUT/LPUART0_TX: R555.1 ; also on sheet 3 11
PTA27/FTM5_CH2/LPSPI1_SOUT/LPUART0_TX_LS: R177.1 TP22.1(Pin1) U506.6(B2)
PTA28/FTM5_CH3/LPSPI1_SCK/LPUART0_RX: R563.1 ; also on sheet 3 11
PTA28/FTM5_CH3/LPSPI1_SCK/LPUART0_RX_LS: R150.1 TP21.1(Pin1) U507.7(B1)
PTA29/FTM5_CH4/LPUART2_TX/LPSPI1_SIN: R554.1 ; also on sheet 3 11
PTA29/FTM5_CH4/LPUART2_TX/LPSPI1_SIN_LS: R154.1 TP25.1(Pin1) U506.7(B1)
PTB8/FTM3_CH0/SAI1_BCLK: R318.1 ; also on sheet 3 11
PTB9/FTM3_CH1/LPI2C0_SCLS: R319.1 ; also on sheet 3 6 11
PTB10/FTM3_CH2/LPI2C0_SDAS: R315.1 ; also on sheet 3 6 11
PTC30/FTM5_CH4/FXIO_D0/LPI2C1_SDAS/FXIO_D0/ADC0_SE30: R320.1 ; also on sheet 3 11
PTC31/FTM5_CH6/FXIO_D1/LPI2C1_SDA/FXIO_D1/ADC0_SE31: R313.1 ; also on sheet 3 11
PTD1/FTM0_CH3/LPSPI1_SIN/FTM2_CH1/SAI0_MCLK: R323.1 ; also on sheet 3 11
PTD13/FTM2_CH4/LPUART1_RX/ENET_TMR1/RTC_CLKOUT: R317.1 ; also on sheet 3 11
PTD14/FTM2_CH5/LPUART1_TX/ENET_TMR0/CLKOUT: R322.1 ; also on sheet 3 11
PTD15/FTM0_CH0/TRACE_D3/LPSPI0_SCK/ENET_TMR2: R332.1 ; also on sheet 3 11
PTD18/FTM5_CH7/FXIO_D2/LPI2C1_SCLS/ADC1_SE16: R321.1 ; also on sheet 3 11
PTD19/FTM6_CH0/FXIO_D3/LPI2C1_SCL/ADC1_SE17: R314.1 ; also on sheet 3 11
PTE0/LPSPI0_SCK/TCLK1/LPI2C1_SDA/SAI0_D2: R328.1 ; also on sheet 3 11
PTE1/LPSPI0_SIN/LPI2C0_HREQ/LPI2C1_SCL/SAI0_D1: R327.1 ; also on sheet 3 11
PTE2/LPSPI0_SOUT/FTM3_CH6/SAI1_SYNC/ADC1_SE10: R316.1 ; also on sheet 3 11
PTE4/CAN0_RX_LS: R127.1 TP13.1(Pin1) U502.6(B2)
PTE4/TRACE_D1/FTM2_CH2/CAN0_RX/FXIO_D6: R520.1 ; also on sheet 3
PTE5/CAN0_TX_LS: R126.1 TP504.1(Pin1) U502.7(B1)
PTE5/TCLK2/FTM2_CH3/CAN0_TX/FXIO_D7: R519.1 ; also on sheet 3
PTE9/FTM0_CH7/LPUART2_CTS/ENET_TMR3: R331.1 ; also on sheet 3 11
PTE10/CLKOUT/LPSPI2_PCS1/FTM2_CH4/FXIO_D4: R310.1 ; also on sheet 3 6 11
PTE11/FTM2_CH5/FXIO_D5: R309.1 ; also on sheet 3 11
PTE15/LPSPI2_SCK/FTM2_CH6/FTM4_FLT1/FXIO_D2: R312.1 ; also on sheet 3 11
PTE16/LPSPI2_SIN/FTM2_CH7/FTM4_FLT0/FXIO_D3: R311.1 ; also on sheet 3 11
PTE19/FTM7_CH7/FTM7_CH7/ADC1_SE25: R528.1 ; also on sheet 3 11
PTE19/FTM7_CH7/FTM7_CH7/ADC1_SE25_LS: R139.2 TP502.1(Pin1) U501.7(B1)
PTE20/FTM4_CH0/FTM4_CH0/ADC1_SE26: R534.1 ; also on sheet 3 11
PTE20/FTM4_CH0/FTM4_CH0/ADC1_SE26_LS: R124.2 TP501.1(Pin1) U501.6(B2)
PVEXT_SBC: C54.1 C57.1 C60.1 R204.2 R527.1 R632.2 TPAD39.1(Pin1) TS11.1 U9.2(VEXT)
SAI0_BCLK: P1.11(A6) R325.2
SAI0_DATA0: P1.9(A5) R326.2
SAI0_DATA1: P1.7(A4) R327.2
SAI0_DATA2: P1.5(A3) R328.2
SAI0_DATA3: P1.3(A2) R329.2
SAI0_MCLK: P1.15(A8) R323.2
SAI0_SYNC: P1.13(A7) R324.2
SBC_CANH: R112.1 R119.1 U9.21(CANH)
SBC_CANL: R134.1 R135.1 U9.22(CANL)
SBC_EN: J15.7(A4) U9.5(EN)
SBC_HVIO1: J14.1(A1) R4.1 TP30.1(Pin1) U9.37(HVIO1)
SBC_HVIO2: J14.3(A2) R203.2 TP28.1(Pin1) U9.36(HVIO2)
SBC_HVIO3: J14.4(B2) U9.35(HVIO3)
SBC_HVIO4: J14.2(B1) U9.34(HVIO4)
SBC_HVIO5: J15.8(B4) U9.33(NC)
SBC_HVIO6: J15.6(B3) U9.32(NC)
SBC_HVIO7: J15.4(B2) U9.31(NC)
SBC_HVIO8: J15.2(B1) U9.30(NC)
SBC_LIMP: D7.C(CATHODE) J15.5(A3) U9.39(LIMP)
SBC_LIN_OUT1: R542.1 R543.1 U9.24(LIN1)
SBC_LIN_OUT2: R530.1 R535.1 U9.25(LIN2)
SBC_OE: R525.1 U500.5(OE) U501.5(OE) U502.5(OE) U503.5(OE) U504.5(OE) U506.5(OE) U507.5(OE)
SBC_RESET: R532.1 TP503.1(Pin1) U503.7(B1)
SPLIT: C15.1 R125.2 R138.1
VCAN_SBC: R526.2 R527.2 U9.20(VCAN)
VSUP: C11.1 C13.1 C14.1 D4.C J12.1 J21.1 L2.1 R13.1 R106.1 R189.1 R215.1 R262.1 R334.1 TP9.1(Pin1) TS5.1 U9.38(BATHS1) ; also on sheet 6
N16745305: C10.1 C12.2
N16745986: C16.1 C21.1 C22.1 L2.2 R106.2 TP16.1(Pin1) U9.26(BAT) U9.43(BATSMPS)
N16746162: C43.1 R163.2 TP24.1(Pin1) U9.28(BATSENSE)
N16749267: C62.2 C64.2 TP34.1(Pin1) U9.40(CAPB)
N16749274: C62.1 C64.1 TP37.1(Pin1) U9.41(CAPA)
N16751208: C63.2 C65.2 TP38.1(Pin1) U9.42(BOOTH1)
N16751220: C63.1 C65.1 L8.1 TP39.1(Pin1) U9.44(L1)
N16751253: C67.2 C69.2 TP40.1(Pin1) U9.48(BOOTH2)
N16751262: C67.1 C69.1 L8.2 TP47.1(Pin1) U9.46(L2)
N16752852: C29.1 U9.27(ADCCAP)
N16754051: C70.1 C71.1 R216.1 TP41.1(Pin1) U9.47(VSMPS)
N16755093: R139.1 R140.2 TPAD30.1(Pin1) U9.11(INTN1)
N16755100: R124.1 R132.2 TPAD29.1(Pin1) U9.13(INTN2)
N16755551: D8.A J12.2
N16755555: D8.C R225.2 R226.2 TP45.1(Pin1)
N16762105: J11.3 R180.1
N16853763: R519.2 U502.2(A1)
N16853765: R520.2 U502.3(A2)
N16854069: R540.2 U504.2(A1)
N16854076: R536.2 U504.3(A2)
N16854778: C512.1 C513.1 C514.1 C515.1 R517.1 R523.1 R632.1 TP500.1(Pin1) U500.8(VCCB) U501.8(VCCB) U502.8(VCCB) U503.8(VCCB) U504.8(VCCB) U506.8(VCCB) U507.8(VCCB)
N16855430: C24.1 C26.1 C30.1 L3.2 R93.1 R97.1 R633.1 TPAD505.1(Pin1)
N16855432: C8.1 C501.1 D500.C TPAD15.1(Pin1) U1.1(VIN)
N16855436: D5.C L3.1 TPAD20.1(Pin1) U1.2(OUT)
N16855465: R92.1 R93.2 R97.2 TPAD23.1(Pin1) U1.3(FB)
N16855504: D500.A J18.2 TPAD8.1(Pin1) TS2.1
N16868078: R554.2 U506.2(A1)
N16868081: R555.2 U506.3(A2)
N16868084: R563.2 U507.2(A1)
N16868087: R564.2 U507.3(A2)
N16990851: DS1.C(CATHODE) R4.2 R500.1
N16990853: DS2.C(CATHODE) Q500.3(COLLECTOR)
N16992788: DS3.C(CATHODE) Q501.3(COLLECTOR)
N16994780: DS1.A(ANODE) R13.2
N16994781: DS2.A(ANODE) R9.2
N16994782: DS3.A(ANODE) R12.2
N17105995: R177.2 U9.7(SDI)
N17106020: R154.2 U9.8(SDO)
N17106045: R150.2 U9.9(SCK)
N17106070: R149.2 U9.10(SCSN)
N17106135: R128.2 U9.17(TXDL1)
N17106160: R129.2 U9.16(RXDL1)
N17106205: R126.2 U9.19(TXDC)
N17106230: R127.2 U9.18(RXDC)
N17110598: D9.A J21.2
N17110600: D9.C R276.2 R279.2 TP54.1(Pin1)
N17111325: R130.2 U9.15(TXDL2)
N17111345: R131.2 U9.14(RXDL2)
N17142860: R511.2 U500.2(A1)
N17142862: R512.2 U500.3(A2)
N17172615: Q500.1(BASE) R502.1 R504.1 TPAD501.1(Pin1)
N17172906: Q501.1(BASE) R503.1 R505.1 TPAD500.1(Pin1)
N17344806: R528.2 U501.2(A1)
N17344809: R534.2 U501.3(A2)
N17345453: R537.2 U503.2(A1)
N17347641: R523.2 U503.6(B2)
N17349405: R531.2 R532.2 U9.12(RSTN)
N17414813: R189.2 U9.29(NC)
N17414865: R215.2 R216.2 U9.1(BATV2)
N17423098: D7.A(ANODE) R262.2
N17437399: C116.1 R203.1 R334.2 SW6.2 SW6.4
N17489769: R153.2 U503.3(A2)
N20620060: P1.17(A9) R322.2
N20620064: P1.27(A14) R317.2
N20620068: P1.45(A23) R332.2
N20620072: P1.47(A24) R331.2
N20620358: P1.31(A16) R315.2
N20620361: P1.29(A15) R316.2
N20620364: P1.25(A13) R318.2
N20620367: P1.23(A12) R319.2
N20620674: P1.21(A11) R320.2
N20620694: P1.19(A10) R321.2
N20620726: P1.33(A17) R314.2
N20620746: P1.35(A18) R313.2
N20620840: P1.37(A19) R312.2
N20620843: P1.39(A20) R311.2
N20620846: P1.41(A21) R310.2
N20620849: P1.43(A22) R309.2

Not connected (* = marked no-connect by the designer): J13 3*; J17 3*

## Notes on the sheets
sheet 1
- SAI Audio
- SAI
- SAI
- SAI
- SAI
- SAI
- SAI
- SAI
- (ENET0_TMR0)
- (I2C_SCL3)
- (I2C_SDA3)
- ENET_I2C_SCL
- (SAI1_DATA0)
- (SAI1_BCLK)
- (ENET1_TMR2)
- ENET_I2C_SDA
- (SAI1_MCLK)
- (SAI1_SYNC)
- (I2C_SCL2)
- (I2C_SDA2)
- (SAI2_DATA0)
- (SAI2_BCLK)
- ENET_SPI_CS1
- (SAI2_SYNC)
- TRACE
- (ENET0_TMR2)
- (SAI2_MCLK)
- (GPIO Control)
sheet 2
- 3.3V Switching Regulator
- Input Voltage 5V, Output 3.3V at 1600mA
- Battery supply
  input for SMPS
- Buck/boost
  HS-CAN/dual LIN
  system basis chip
- SMPS output
  voltage
- Low
  ESR
- Low
  ESR
- Bbootstrap capacitor
- Layout note: follow IC datasheet recommandations for
  PCB layout and thermal dissipation
- TX / RX
  POKA-YOKE: Place both jumpers with
  the same orientation and provide
  same airgap between their terminals
  in a square fashion.
- LIN1and LIN2 Bus
  routed to I/O
  Connectors
- SBC_LIN1TX
- SBC_LIN1RX
- CAN Bus
  routed to I/O
  Connectors
- SBC_LIN2TX
- SBC_LIN2RX
- HVIO1-8
  Bidirectional
  open-drain low-side
  driver with
  integrated pull-up
  resistance
- Test and reference points
- SBC Wake-Up
- TRACE
- TX / RX
  POKA-YOKE: Place both jumpers with
  the same orientation and provide
  same airgap between their terminals
  in a square fashion.
- CAN /FD Interface
- Power LED Indicators
- LIN1 Interface
- Master
  option
- - LIN 2.x compliant
  - Compliant with SAE J2602
  - Downward compatible with LIN 1.3
  - Integrated LIN slave termination
- SBC_SPI_MOSI
- SBC_SPI_MISO
- LIN Bus 1
- ISO 11898-2:201x (upcoming merged ISO
  11898-2/5/6) compliant 1 Mbit/s high-speed
  CAN transceiver supporting CAN FD active
  communication up to 2 Mbit/s in the CAN
  FD data field
- SBC_SPI_CLK
- SBC_SPI_CS
- Global Supply Jumpers and
   Power Selection
- LIN2 Interface
- Master
  option
- - LIN 2.x compliant
  - Compliant with SAE J2602
  - Downward compatible with LIN 1.3
  - Integrated LIN slave termination
- LIN Bus 2
